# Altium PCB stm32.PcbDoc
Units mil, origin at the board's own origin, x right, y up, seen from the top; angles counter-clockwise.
Board outline 6010.03 x 5085.03 mil, 2 copper layers (Top Layer, Bottom Layer); 115 components, 0 nets, 494 pads, 8 vias.
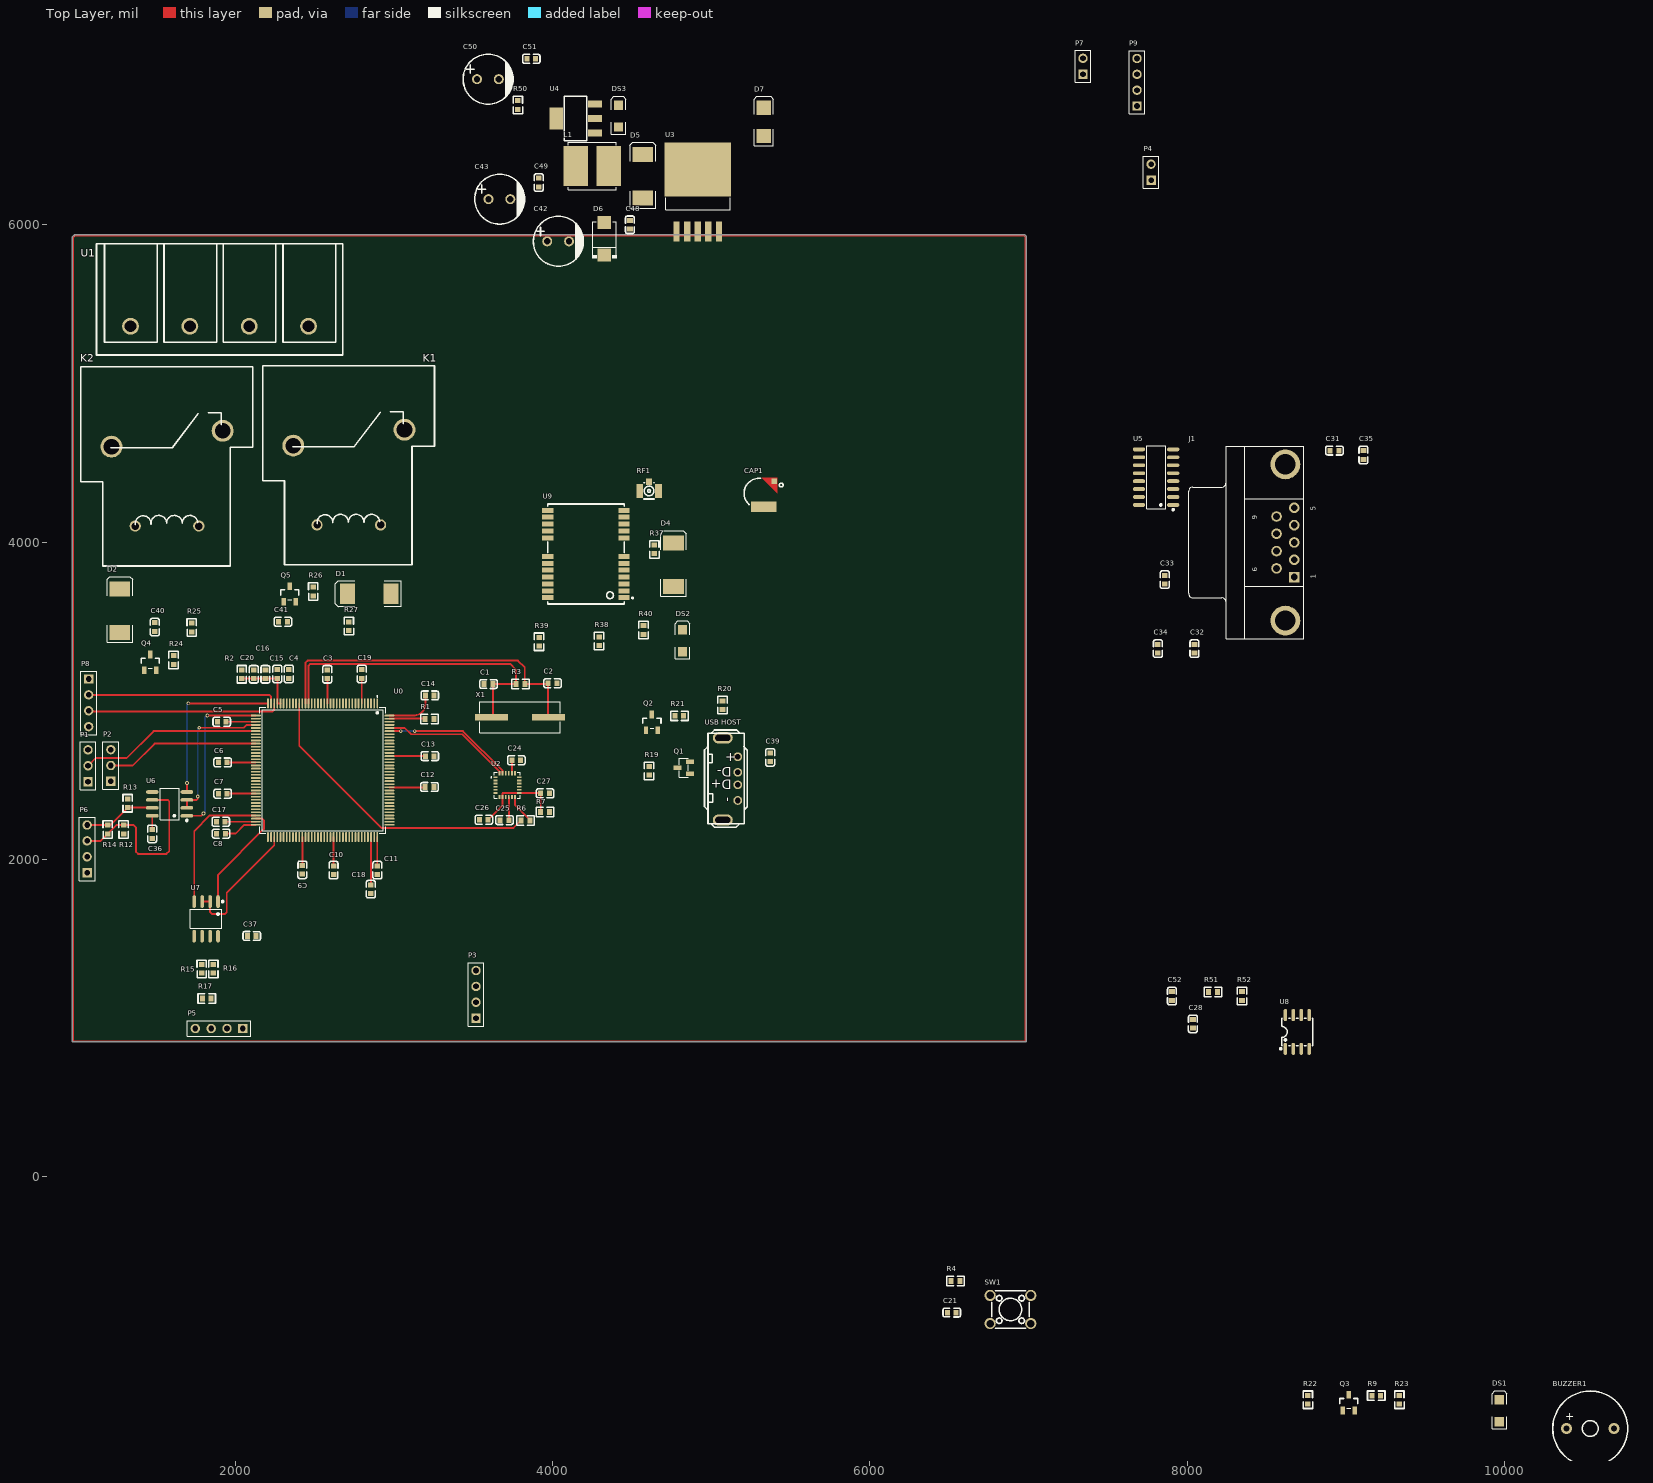
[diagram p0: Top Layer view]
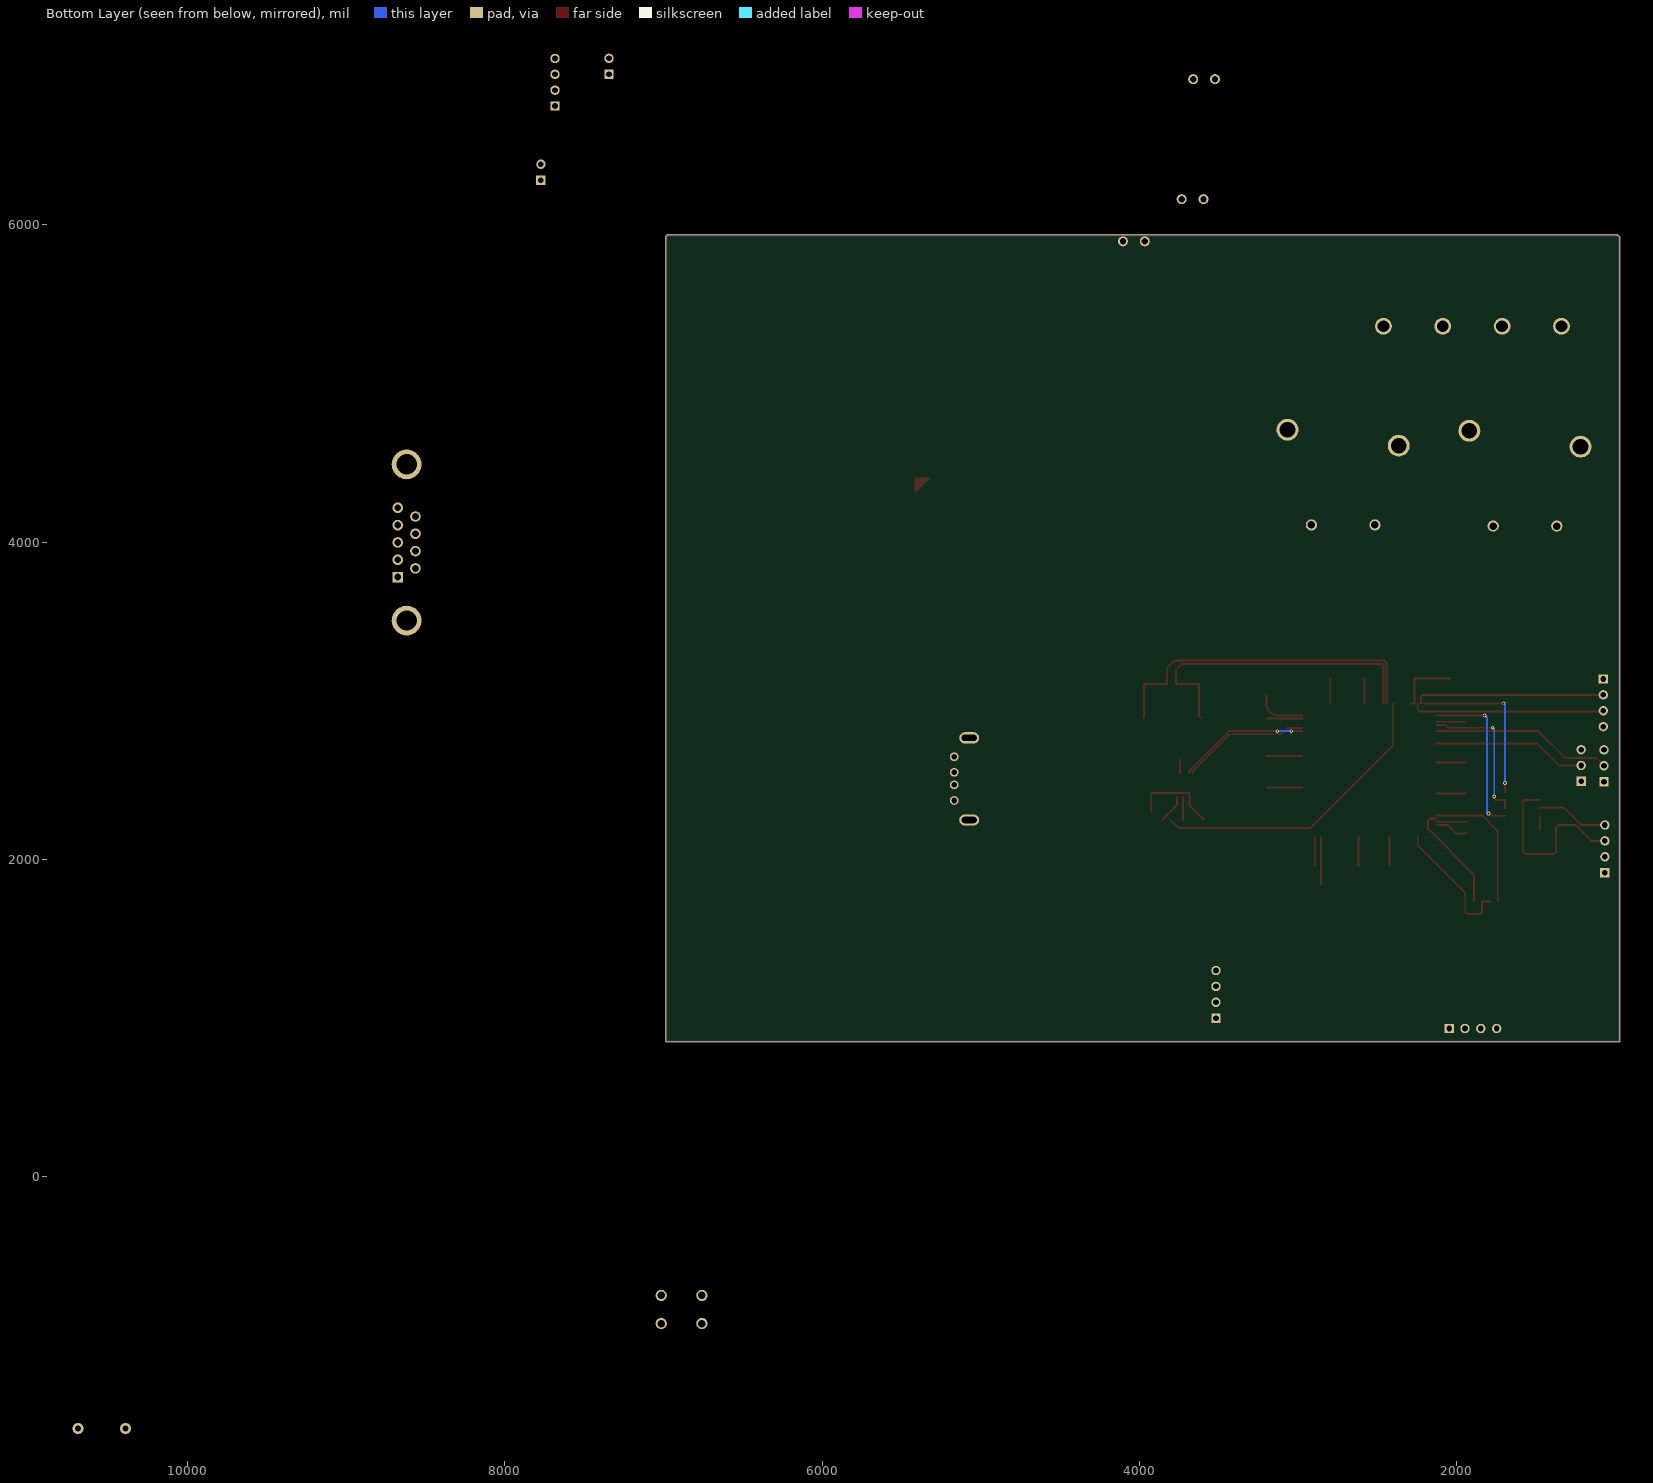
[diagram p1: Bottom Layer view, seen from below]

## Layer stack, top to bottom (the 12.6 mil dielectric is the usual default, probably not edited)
Top Solder: solder mask 0.4, Solder Resist, Dk 3.5
Top Layer: signal copper 1.4
Dielectric 1: dielectric 12.6, FR-4, Dk 4.8
Bottom Layer: signal copper 1.4
Bottom Solder: solder mask 0.4, Solder Resist, Dk 3.5

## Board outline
974.99,855 ccw(c980,855) 980,849.99 6980,849.99 ccw(c6980,855) 6985.02,855 6985.02,5925 ccw(c6980,5925) 6980.02,5930.02 ccw(c6975,5930) 6975,5935.02 990,5935.02 ccw(c990,5930) 986.44,5933.53 986.45,5933.55 976.45,5923.55 976.47,5923.56 ccw(c980,5920) 974.99,5920

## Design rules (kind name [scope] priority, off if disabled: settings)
Clearance [All] p1: gap=10
PolygonConnect [All] p1: connectstyle=Relief reliefconductorwidth=10 reliefentries=4 polygonreliefangle="90 Angle" airgapwidth=10
RoomDefinition STM32F407_V2.0 [InComponentClass('STM32F407_V2.0')] p1: confinementstyle=ConfineIn formatcopy=TRUE lockcomponents=FALSE outline -29946.22,-17788.74 -27946.22,-17788.74 -27946.22,-16788.74 -29946.22,-16788.74
RoutingVias [All] p1: holewidth=28 width=50 viastyle="Through Hole" minholewidth=28 minwidth=50 maxholewidth=28 maxwidth=50
SolderMaskExpansion [All] p1: expansion=4
Width [All] p1: maxlimit=10 minlimit=10 preferedwidth=10
30 further rules are at their usual default settings.

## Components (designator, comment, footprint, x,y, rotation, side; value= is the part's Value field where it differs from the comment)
BUZZER1 "TMB12A03" BUZ-TH_BD12.0-P7.60-D0.6-FD 10539.9,-1586.03 r0 top
C1 "22nF" SMD_CAP_0603 3597.29,3105.71 r180 top
C2 "22nF" SMD_CAP_0603 4000.83,3109.65 r0 top
C3 "100nF" SMD_CAP_0603 2581.54,3166.73 r90 top
C4 "100nF" SMD_CAP_0603 2339.41,3168.7 r90 top
C5 "100nF" SMD_CAP_0603 1916.18,2867.52 r180 top
C6 "100nF" SMD_CAP_0603 1922.08,2611.61 r180 top
C7 "100nF" SMD_CAP_0603 1922.09,2414.76 r180 top
C8 "100nF" SMD_CAP_0603 1912.24,2162.8 r180 top
C9 "100nF" SMD_CAP_0603 2424.06,1934.45 r270 top
C10 "100nF" SMD_CAP_0603 2620.91,1932.48 r90 top
C11 "100nF" SMD_CAP_0603 2896.5,1932.48 r270 top
C12 "100nF" SMD_CAP_0603 3225.24,2456.1 r0 top
C13 "100nF" SMD_CAP_0603 3227.21,2650.98 r0 top
C14 "100nF" SMD_CAP_0603 3227.21,3032.87 r0 top
C15 "10uF" SMD_CAP_0603 2266.57,3168.7 r90 top
C16 "100nF" SMD_CAP_0603 2191.77,3166.73 r90 top
C17 "225nF" SMD_CAP_0603 1910.28,2237.6 r180 top
C18 "225nF" SMD_CAP_0603 2855.16,1812.4 r270 top
C19 "100nF" SMD_CAP_0603 2798.07,3168.7 r270 top
C20 "225nF" SMD_CAP_0603 2118.94,3166.73 r90 top
C21 "100nF" SMD_CAP_0603 6516.38,-855.67 r0 top
C24 "10uF" SMD_CAP_0603 3772.48,2625.39 r180 top
C25 "100nF" SMD_CAP_0603 3697.68,2247.44 r0 top
C26 "10uF" SMD_CAP_0603 3567.76,2249.41 r0 top
C27 "100nF" SMD_CAP_0603 3953.58,2416.73 r180 top
C28 "100nF" SMD_CAP_0603 8036.26,963.98 r90 top
C31 "100nF" SMD_CAP_0603 8927.85,4576.14 r0 top
C32 "100nF" SMD_CAP_0603 8045.97,3328.11 r90 top
C33 "100nF" SMD_CAP_0603 7858.96,3763.15 r90 top
C34 "100nF" SMD_CAP_0603 7815.65,3328.11 r90 top
C35 "100nF" SMD_CAP_0603 9110.92,4548.58 r90 top
C36 "100nF/50V" SMD_CAP_0603 1477.2,2160.83 r270 top
C37 "100nF/50V" SMD_CAP_0603 2105.16,1517.13 r0 top
C39 "100nF" SMD_CAP_0603 5372.73,2643.07 r90 top
C40 "100nF" SMD_CAP_0603 1494.81,3463.93 r90 top
C41 "100nF" SMD_CAP_0603 2301.88,3497.4 r0 top
C42 "680uF" CAP-TH_BD8.0-P3.50-D1.0-FD 4036.15,5895.03 r0 top
C43 "220uF" CAP-TH_BD8.0-P3.50-D1.0-FD 3666.08,6160.78 r0 top
C48 "100nF" SMD_CAP_0603 4488.91,5999.37 r90 top
C49 "100nF" SMD_CAP_0603 3914.11,6265.11 r90 top
C50 "220uF" CAP-TH_BD8.0-P3.50-D1.0-FD 3593.25,6916.68 r0 top
C51 "100nF" SMD_CAP_0603 3866.87,7044.64 r0 top
C52 "10nF/50V/10%" SMD_CAP_0603 7904.27,1139.13 r90 top
CAP1 "70mF" CAP-TH_XH414HG 5392.44,4324.17 r0 top
D1 "Diode" SMC 2846.3,3674.61 r180 top
D2 "Diode" SMC 1274.33,3568.26 r90 top
D4 "Diode" SMC 4762.64,3857.68 r90 top
D5 "Diode" SMC 4569.61,6304.48 r90 top
D6 "SMBJ8.0A" SMB_L4.6-W3.6-LS5.3-RD 4327.49,5910.78 r90 top
D7 "SK54" SMB 5331.43,6647 r90 top
DS1 "LED0" 3.2X1.6X1.1 9967.07,-1473.83 r90 top
DS2 "LED0" 3.2X1.6X1.1 4819.61,3377.32 r90 top
DS3 "LED2" 3.2X1.6X1.1 4416.08,6684.4 r90 top
J1 "D Connector 9" DSUB1.385-2H9 8244.78,3997.4 r90 top
K1 "HF105F-1/012D-1HS" RELAY-TH_HF105F-XXX-1HXXX-XXX 2717.36,4407.68 r0 top
K2 "HF105F-1/012D-1HS" RELAY-TH_HF105F-XXX-1HXXX-XXX 1571.69,4400.98 r0 top
L1 "33uH" IND-SMD_L7.0-W6.8 4250.72,6369.44 r0 top
P1 "Hall1" HDR1X3 1073.66,2490.35 r90 top
P2 "Hall2" HDR1X3 1217.36,2491.93 r90 top
P3 "Header 4" HDR1X4 3518.54,999.8 r90 top
P4 "Header 2" HDR1X2 7772.34,6280.86 r90 top
P5 "Header 4" HDR1X4 2049.65,934.45 r180 top
P6 "Header 4" HDR1X4 1067.76,1916.73 r90 top
P7 "Header 2" HDR1X2 7343.21,6948.18 r90 top
P8 "Header 4" HDR1X4 1077.6,3136.81 r270 top
P9 "Header 4" HDR1X4 7683.77,6747.4 r90 top
Q1 "SI2301" SOT-23-3_L2.9-W1.3-P1.90-LS2.4-BR 4827.46,2578.11 r0 top
Q2 "S8050" NUP2105LT1G 4626.68,2863.54 r0 top
Q3 "S8050" NUP2105LT1G 9018.25,-1422.65 r0 top
Q4 "S8050" NUP2105LT1G 1465.28,3241.49 r0 top
Q5 "S8050" NUP2105LT1G 2345.18,3672.59 r0 top
R1 "0R" SMD_RES_0603 3225.24,2885.24 r180 top
R2 "10R" SMD_RES_0603 2042.17,3166.73 r270 top
R3 "1M" SMD_RES_0603 3798.07,3105.71 r180 top
R4 "10k" SMD_RES_0603 6540,-656.85 r0 top
R6 "1k" SMD_RES_0603 3829.57,2245.47 r180 top
R7 "10R" SMD_RES_0603 3953.58,2298.62 r180 top
R9 "510R" SMD_RES_0603 9191.48,-1379.34 r0 top
R12 "360R" SMD_RES_0603 1298.07,2188.38 r90 top
R13 "360R" SMD_RES_0603 1323.66,2353.74 r90 top
R14 "120R" SMD_RES_0603 1197.68,2188.38 r270 top
R15 "360R" SMD_RES_0603 1790.2,1310.43 r90 top
R16 "360R" SMD_RES_0603 1863.03,1310.43 r270 top
R17 "120R" SMD_RES_0603 1821.69,1123.43 r180 top
R19 "10k" SMD_RES_0603 4609.09,2558.46 r90 top
R20 "100k" SMD_RES_0603 5071.69,2971.85 r90 top
R21 "4.7K" SMD_RES_0603 4799.91,2904.88 r0 top
R22 "10K" SMD_RES_0603 8760.38,-1404.93 r90 top
R23 "1K" SMD_RES_0603 9337.15,-1404.93 r90 top
R24 "4.7K" SMD_RES_0603 1612.91,3257.24 r90 top
R25 "47K" SMD_RES_0603 1727.09,3461.96 r90 top
R26 "4.7K" SMD_RES_0603 2492.82,3688.34 r90 top
R27 "47K" SMD_RES_0603 2717.24,3469.84 r90 top
R37 "120R" SMD_RES_0603 4642.44,3954.09 r90 top
R38 "510R" SMD_RES_0603 4294.13,3375.39 r90 top
R39 "510R" SMD_RES_0603 3916.18,3371.46 r90 top
R40 "510R" SMD_RES_0603 4573.55,3446.22 r90 top
R50 "2K" SMD_RES_0603 3782.22,6753.3 r90 top
R51 "60.4R/5%/1/8W" SMD_RES_0603 8162.14,1164.72 r0 top
R52 "60.4R/5%/1/8W" SMD_RES_0603 8345.21,1139.13 r90 top
RF1 "KH-IPEX-K501-29" ANT-SMD_KH-IPEX-K501-29 4608.98,4351.73 r0 top
SW1 "SW" SW-TH_4P-L6.0-W6.0-P4.50-LS6.5 6886.36,-836.03 r0 top
U0 "STM32F407ZGT6" LQFP-144_L20.0-W20.0-P0.50-LS22.0-BL 2552.01,2562.4 r180 top locked
U1 "DBT50B-9.5-4P" CONN-TH_DBT50B-9.5-4P 1902.4,5359.65 r180 top
U2 "MPU6050" QFN-24_L4.0-W4.0-P0.50-BL-EP2.6 3715.39,2467.91 r270 top
U3 "LM2596R-5.0" TO-263-5_L10.2-W8.6-P1.70-LS14.4-TL 4916.07,6152.91 r90 top
U4 "AMS1117" SOT-223_L6.7-W3.5-P2.30-BR 4146.39,6668.65 r0 top
U5 "MAX3232ID" SOIC-16_L9.9-W3.9-P1.27-LS6.0-BL 7803.84,4408.82 r90 top
U6 "SP3485EEN" SOP-8_L5.0-W4.0-P1.27-LS6.0-BL 1587.44,2349.8 r90 top
U7 "SP3485EEN" SOP-8_L5.0-W4.0-P1.27-LS6.0-BL 1817.76,1625.39 r180 top
U8 "TJA1050T/CM,118" SOIC-8_L5.0-W4.0-P1.27-LS6.0-BL 8693.74,912.8 r0 top
U9 "KH-1612-UB8X" GPSM-SMD_KH-1612-UBXX 4211.46,3924.61 r0 top
"USB HOST" "C16722" USB-A-TH_4P-V-F_13.7MM 5120.77,2507.24 r0 top
X1 "8MHz" HC-49S_L11.4-W4.8 3796.1,2895.08 r180 top

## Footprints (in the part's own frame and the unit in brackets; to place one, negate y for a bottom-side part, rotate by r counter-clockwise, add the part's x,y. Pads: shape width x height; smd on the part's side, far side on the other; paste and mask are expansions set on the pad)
3.2X1.6X1.1 [mm] "SMT LED; 2 Flat Leads"
  rect 1.5x1.5 smd: 1(-1.75,0) 2(1.75,0)
  silkscreen extent -2.9,-1.15 3.2,1.15
ANT-SMD_KH-IPEX-K501-29 [mm]
  rect 1.1x2.2 smd: 1(-1.5,-0.75) 3(1.5,-0.75)
  rect 1x1.05 smd: 2(0,0.75)
  silkscreen extent -0.84,-2.05 0.84,0.55
BUZ-TH_BD12.0-P7.60-D0.6-FD [mm]
  round 1.8 hole 1: 1(-3.8,0) 2(3.8,0)
  silkscreen extent -6,-6 6,6
CAP-TH_BD8.0-P3.50-D1.0-FD [mm]
  round 1.6 hole 1: 1(-1.75,0) 2(1.75,0)
  silkscreen extent -3.96,-4 4.04,4
CAP-TH_XH414HG [mil]
  round 0 smd: 1(-23.48,57.63)
  rect 35x35 smd: 1(5,60)
  rect 161.4x66.93 smd: 2(-60.88,-100.84)
  Top Layer region: -72.69,82.24 25.74,82.24 25.74,-16.19
  silkscreen extent -185,-89 61,77
CONN-TH_DBT50B-9.5-4P [mm]
  round 2.7 hole 1.9: 1(-14.25,0) 2(-4.75,0) 3(4.75,0) 4(14.25,0)
  silkscreen extent -19.7,-13.21 19.7,4.6
DSUB1.385-2H9 [mm] "Connector; D Subminiature; 9 Position; Right Angle; Pitch 1.385 mm"
  rect 1.69x1.69 hole 1.09: 1(-5.54,-10.92)
  round 1.69 hole 1.09: 2(-2.77,-10.92) 3(0,-10.92) 4(2.77,-10.92) 5(5.54,-10.92) 6(-4.155,-8.08) 7(-1.385,-8.08) 8(1.385,-8.08) 9(4.155,-8.08)
  round 4.76 hole 3.26: 10(-12.495,-9.5) 11(12.495,-9.5)
  silkscreen extent -15.4,-12.4 15.4,6
GPSM-SMD_KH-1612-UBXX [mm]
  rect 1.8x0.8 smd: 1(6.1,-7) 2(6.1,-5.9) 3(6.1,-4.8) 4(6.1,-3.7) 5(6.1,-2.6) 6(6.1,-1.5) 7(6.1,-0.4) 8(6.1,2.6) 9(6.1,3.7) 10(6.1,4.8) 11(6.1,5.9) 12(6.1,7) 13(-6.1,7) 14(-6.1,5.9) 15(-6.1,4.8) 16(-6.1,3.7) 17(-6.1,2.6) 18(-6.1,-0.4) 19(-6.1,-1.5) 20(-6.1,-2.6) 21(-6.1,-3.7) 22(-6.1,-4.8) 23(-6.1,-5.9) 24(-6.1,-7)
  silkscreen extent -6.1,-8 7.58,8
HC-49S_L11.4-W4.8 [mm] "晶振8M"
  rect 5.274x1.02 smd: 1(4.553,0) 2(-4.553,0)
  silkscreen extent -6.43,-2.48 6.43,2.48
HDR1X2 [mm] "Connector; Header; 2 Position"
  rect 1.5x1.5 hole 0.9: 1(0,0)
  round 1.5 hole 0.9: 2(2.54,0)
  silkscreen extent -1.27,-1.27 3.81,1.27
HDR1X3 [mm] "Connector; Header; 3 Position"
  rect 1.5x1.5 hole 0.9: 1(0,0)
  round 1.5 hole 0.9: 2(2.54,0) 3(5.08,0)
  silkscreen extent -1.27,-1.27 6.35,1.27
HDR1X4 [mm] "Connector; Header; 4 Position"
  rect 1.5x1.5 hole 0.9: 1(0,0)
  round 1.5 hole 0.9: 2(2.54,0) 3(5.08,0) 4(7.62,0)
  silkscreen extent -1.27,-1.27 8.89,1.27
IND-SMD_L7.0-W6.8 [mm]
  rect 3.924x6.42 smd: 1(2.628,0) 2(-2.628,0)
  silkscreen extent -3.83,-3.83 3.83,3.83
LQFP-144_L20.0-W20.0-P0.50-LS22.0-BL [mm] "MCU"
  oval 0.28x1.6 smd: 1(-8.75,-10.7) 2(-8.25,-10.7) 3(-7.75,-10.7) 4(-7.25,-10.7) 5(-6.75,-10.7) 6(-6.25,-10.7) 7(-5.75,-10.7) 8(-5.25,-10.7) 9(-4.75,-10.7) 10(-4.25,-10.7) 11(-3.75,-10.7) 12(-3.25,-10.7) 13(-2.75,-10.7) 14(-2.25,-10.7) 15(-1.75,-10.7) 16(-1.25,-10.7) 17(-0.75,-10.7) 18(-0.25,-10.7) 19(0.25,-10.7) 20(0.75,-10.7) 21(1.25,-10.7) 22(1.75,-10.7) 23(2.25,-10.7) 24(2.75,-10.7) 25(3.25,-10.7) 26(3.75,-10.7) 27(4.25,-10.7) 28(4.75,-10.7) 29(5.25,-10.7) 30(5.75,-10.7) 31(6.25,-10.7) 32(6.75,-10.7) 33(7.25,-10.7) 34(7.75,-10.7) 35(8.25,-10.7) 36(8.75,-10.7) 73(8.75,10.7) 74(8.25,10.7) 75(7.75,10.7) 76(7.25,10.7) 77(6.75,10.7) 78(6.25,10.7) 79(5.75,10.7) 80(5.25,10.7) 81(4.75,10.7) 82(4.25,10.7) 83(3.75,10.7) 84(3.25,10.7) 85(2.75,10.7) 86(2.25,10.7) 87(1.75,10.7) 88(1.25,10.7) 89(0.75,10.7) 90(0.25,10.7) 91(-0.25,10.7) 92(-0.75,10.7) 93(-1.25,10.7) 94(-1.75,10.7) 95(-2.25,10.7) 96(-2.75,10.7) 97(-3.25,10.7) 98(-3.75,10.7) 99(-4.25,10.7) 100(-4.75,10.7) 101(-5.25,10.7) 102(-5.75,10.7) 103(-6.25,10.7) 104(-6.75,10.7) 105(-7.25,10.7) 106(-7.75,10.7) 107(-8.25,10.7) 108(-8.75,10.7)
  oval 1.6x0.28 smd: 37(10.7,-8.75) 38(10.7,-8.25) 39(10.7,-7.75) 40(10.7,-7.25) 41(10.7,-6.75) 42(10.7,-6.25) 43(10.7,-5.75) 44(10.7,-5.25) 45(10.7,-4.75) 46(10.7,-4.25) 47(10.7,-3.75) 48(10.7,-3.25) 49(10.7,-2.75) 50(10.7,-2.25) 51(10.7,-1.75) 52(10.7,-1.25) 53(10.7,-0.75) 54(10.7,-0.25) 55(10.7,0.25) 56(10.7,0.75) 57(10.7,1.25) 58(10.7,1.75) 59(10.7,2.25) 60(10.7,2.75) 61(10.7,3.25) 62(10.7,3.75) 63(10.7,4.25) 64(10.7,4.75) 65(10.7,5.25) 66(10.7,5.75) 67(10.7,6.25) 68(10.7,6.75) 69(10.7,7.25) 70(10.7,7.75) 71(10.7,8.25) 72(10.7,8.75) 109(-10.7,8.75) 110(-10.7,8.25) 111(-10.7,7.75) 112(-10.7,7.25) 113(-10.7,6.75) 114(-10.7,6.25) 115(-10.7,5.75) 116(-10.7,5.25) 117(-10.7,4.75) 118(-10.7,4.25) 119(-10.7,3.75) 120(-10.7,3.25) 121(-10.7,2.75) 122(-10.7,2.25) 123(-10.7,1.75) 124(-10.7,1.25) 125(-10.7,0.75) 126(-10.7,0.25) 127(-10.7,-0.25) 128(-10.7,-0.75) 129(-10.7,-1.25) 130(-10.7,-1.75) 131(-10.7,-2.25) 132(-10.7,-2.75) 133(-10.7,-3.25) 134(-10.7,-3.75) 135(-10.7,-4.25) 136(-10.7,-4.75) 137(-10.7,-5.25) 138(-10.7,-5.75) 139(-10.7,-6.25) 140(-10.7,-6.75) 141(-10.7,-7.25) 142(-10.7,-7.75) 143(-10.7,-8.25) 144(-10.7,-8.75)
  silkscreen extent -10.08,-11.9 10.08,10.08
NUP2105LT1G [mm]
  rect 0.7x1.25 smd: 1(-0.95,-1.25) 2(0.95,-1.25) 3(0,1.25)
  silkscreen extent -1.46,-0.9 1.46,0.65
QFN-24_L4.0-W4.0-P0.50-BL-EP2.6 [mm]
  rect 0.28x0.665 smd: 1(-1.25,-1.907) 2(-0.75,-1.907) 3(-0.25,-1.907) 4(0.25,-1.907) 5(0.75,-1.907) 6(1.25,-1.907) 13(1.25,1.907) 14(0.75,1.907) 15(0.25,1.907) 16(-0.25,1.907) 17(-0.75,1.907) 18(-1.25,1.907)
  rect 0.665x0.28 smd: 7(1.907,-1.25) 8(1.907,-0.75) 9(1.907,-0.25) 10(1.907,0.25) 11(1.907,0.75) 12(1.907,1.25) 19(-1.907,1.25) 20(-1.907,0.75) 21(-1.907,0.25) 22(-1.907,-0.25) 23(-1.907,-0.75) 24(-1.907,-1.25)
  silkscreen extent -2.08,-2.61 2.08,2.08
RELAY-TH_HF105F-XXX-1HXXX-XXX [mm]
  round 3.5 hole 2.5: 2(8.9,7.62) 5(-8.9,5.08)
  round 1.8 hole 1.2: 3(5.08,-7.62) 4(-5.1,-7.62)
  silkscreen extent -13.8,-14.02 13.7,17.88
SMB [mm] "DO-214-AA/SMB; 2 C-Bend Leads; Body 5.3 x 3.6 mm, inc. leads (LxW)"
  rect 2.3x2.3 smd: 1(-2.25,0) 2(2.25,0)
  silkscreen extent -3.8,-1.55 4.1,1.55
SMB_L4.6-W3.6-LS5.3-RD [mil]
  rect 80.61x86.31 smd: 1(-102.71,0) 2(102.71,0)
  silkscreen extent -123,-77 108,77
SMC [mm] "DO-214-AB/SMC; 2 C-Bend Leads; Body 7.9 x 5.9 mm, inc. leads (LxW)"
  rect 2.4x3.3 smd: 1(-3.475,0) 2(3.475,0)
  silkscreen extent -5.07,-2.05 5.43,2.05
SMD_CAP_0603 [mm]
  rect 0.8x0.9 smd: 1(-0.7,0) 2(0.7,0)
  silkscreen extent -1.4,-0.7 1.4,0.72
SMD_RES_0603 [mm]
  rect 0.8x0.9 smd: 1(-0.7,0) 2(0.7,0)
  silkscreen extent -1.4,-0.75 1.4,0.76
SOIC-8_L5.0-W4.0-P1.27-LS6.0-BL [mil]
  oval 22.38x76.78 smd: 1(-75,-106.5) 2(-25,-106.5) 3(25,-106.5) 4(75,-106.5) 5(75,106.5) 6(25,106.5) 7(-25,106.5) 8(-75,106.5)
  silkscreen extent -110,-112 98,87
SOIC-16_L9.9-W3.9-P1.27-LS6.0-BL [mil]
  oval 23.7x77.6 smd: 1(-175,-107.7) 2(-125,-107.7) 3(-75,-107.7) 4(-25,-107.7) 5(25,-107.7) 6(75,-107.7) 7(125,-107.7) 8(175,-107.7) 9(175,107.7) 10(125,107.7) 11(75,107.7) 12(25,107.7) 13(-25,107.7) 14(-75,107.7) 15(-125,107.7) 16(-175,107.7)
  silkscreen extent -211,-114 198,60
SOP-8_L5.0-W4.0-P1.27-LS6.0-BL [mil]
  oval 22.6x80.14 smd: 1(-75,-108.97) 2(-25,-108.97) 3(25,-108.97) 4(75,-108.97) 5(75,108.97) 6(25,108.97) 7(-25,108.97) 8(-75,108.97)
  silkscreen extent -110,-115 99,60
SOT-23-3_L2.9-W1.3-P1.90-LS2.4-BR [mm]
  rect 1.25x0.7 smd: 1(1,-0.95) 2(1,0.95) 3(-1,0)
  silkscreen extent -0.73,-1.53 0.73,1.53
SOT-223_L6.7-W3.5-P2.30-BR [mm]
  rect 2.2x1.1 smd: 1(3.099,-2.3) 2(3.099,0) 3(3.099,2.3)
  rect 2.2x3.5 smd: 4(-3.099,0)
  silkscreen extent -1.8,-3.55 1.8,3.55
SW-TH_4P-L6.0-W6.0-P4.50-LS6.5 [mm]
  round 1.8 hole 1.2: 1(-3.25,2.25) 2(3.25,2.25) 3(-3.25,-2.25) 4(3.25,-2.25)
  silkscreen extent -3,-3 3,3
TO-263-5_L10.2-W8.6-P1.70-LS14.4-TL [mm]
  rect 3.183x1.02 smd: 1(-4.953,3.4) 2(-4.953,1.7) 3(-4.953,0) 4(-4.953,-1.7) 5(-4.953,-3.4)
  rect 8.705x10.587 smd: 6(4.953,0)
  silkscreen extent -1.52,-5.17 0.45,5.17
USB-A-TH_4P-V-F_13.7MM [mm]
  round 1.4 hole 0.92: 1(1.2,3.551) 2(1.2,1.052) 3(1.2,-0.947) 4(1.2,-3.447)
  oval 3.2x1.8 hole 1 slot 2.4 at 0 deg: 5(-1.2,-6.571) 6(-1.2,6.571)
  silkscreen extent -4.12,-7.74 2.74,7.83

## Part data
BUZZER1: "蜂鸣器"
C1 C2 C3 C4 C5 C6 C7 C8 C9 C10 C11 C12 C13 C14 C15 C16 C17 C18 C21 C24 C25 C26 C27 C28 C31 C32 C33 C34 C35 C36 C37 C39 C40 C41 C52: library part Cap, "Capacitor"
C19 C20: library part Cap, "陶瓷电容"
CAP1: library part "Super Cap"
D1 D2 D4 D5: "Default Diode"
D6: library part SMBJ8.0A_C726816
D7: library part "D Schottky", "Schottky Diode"
DS1 DS2: library part LED2, "Typical RED, GREEN, YELLOW, AMBER GaAs LED"
DS3: "Typical RED, GREEN, YELLOW, AMBER GaAs LED"
J1: "Receptacle Assembly, 9 Position, Right Angle"
K1 K2: "继电器"
P1 P2: library part "Header 3", "Header, 3-Pin"
P3 P5 P6 P8 P9: "Header, 4-Pin"
P4 P7: "Header, 2-Pin"
Q1: library part SI2301_C427391
Q2 Q3 Q4 Q5: library part NPN, "NPN Bipolar Transistor"
R1 R2 R3 R4 R6 R7: library part Res1, "Resistor"
R9 R40 R50: library part Res1, "水泥电阻"
R12 R13 R14 R15 R16 R17 R19 R20 R21 R22 R23 R24 R25 R26 R27 R37 R38 R39 R51 R52: library part "Res Semi", "Semiconductor Resistor"
RF1: "天线插座"
U0: "MCU"
U1: "接线端子"
U2: library part MPU-6050_C24112, "陀螺仪"
U4: library part ASM1117
U9: "GPS"
"USB HOST": "USB_HOST"
X1: "贴片晶振"

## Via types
v1: diameter 23.62, hole 11.81, Top Layer to Bottom Layer, tented both sides, 8 vias

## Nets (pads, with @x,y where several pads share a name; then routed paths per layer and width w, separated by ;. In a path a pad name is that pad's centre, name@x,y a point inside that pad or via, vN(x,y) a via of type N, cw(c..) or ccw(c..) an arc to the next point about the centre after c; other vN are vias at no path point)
pads on no net: "USB HOST.1" "USB HOST.2" "USB HOST.3" "USB HOST.4" "USB HOST.5" "USB HOST.6" BUZZER1.1 BUZZER1.2 C1.1 C1.2 C2.1 C2.2 C3.1 C3.2 C4.1 C4.2 C5.1 C5.2 C6.1 C6.2 C7.1 C7.2 C8.1 C8.2 C9.1 C9.2 C10.1 C10.2 C11.1 C11.2 C12.1 C12.2 C13.1 C13.2 C14.1 C14.2 C15.1 C15.2 C16.1 C16.2 C17.1 C17.2 C18.1 C18.2 C19.1 C19.2 C20.1 C20.2 C21.1 C21.2 C24.1 C24.2 C25.1 C25.2 C26.1 C26.2 C27.1 C27.2 C28.1 C28.2 C31.1 C31.2 C32.1 C32.2 C33.1 C33.2 C34.1 C34.2 C35.1 C35.2 C36.1 C36.2 C37.1 C37.2 C39.1 C39.2 C40.1 C40.2 C41.1 C41.2 C42.1 C42.2 C43.1 C43.2 C48.1 C48.2 C49.1 C49.2 C50.1 C50.2 C51.1 C51.2 C52.1 C52.2 CAP1.1 CAP1.2 D1.1 D1.2 D2.1 D2.2 D4.1 D4.2 D5.1 D5.2 D6.1 D6.2 D7.1 D7.2 DS1.1 DS1.2 DS2.1 DS2.2 DS3.1 DS3.2 J1.1 J1.2 J1.3 J1.4 J1.5 J1.6 J1.7 J1.8 J1.9 J1.10 J1.11 K1.2 K1.3 K1.4 K1.5 K2.2 K2.3 K2.4 K2.5 L1.1 L1.2 P1.1 P1.2 P1.3 P2.1 P2.2 P2.3 P3.1 P3.2 P3.3 P3.4 P4.1 P4.2 P5.1 P5.2 P5.3 P5.4 P6.1 P6.2 P6.3 P6.4 P7.1 P7.2 P8.1 P8.2 P8.3 P8.4 P9.1 P9.2 P9.3 P9.4 Q1.1 Q1.2 Q1.3 Q2.1 Q2.2 Q2.3 Q3.1 Q3.2 Q3.3 Q4.1 Q4.2 Q4.3 Q5.1 Q5.2 Q5.3 R1.1 R1.2 R2.1 R2.2 R3.1 R3.2 R4.1 R4.2 R6.1 R6.2 R7.1 R7.2 R9.1 R9.2 R12.1 R12.2 R13.1 R13.2 R14.1 R14.2 R15.1 R15.2 R16.1 R16.2 R17.1 R17.2 R19.1 R19.2 R20.1 R20.2 R21.1 R21.2 R22.1 R22.2 R23.1 R23.2 R24.1 R24.2 R25.1 R25.2 R26.1 R26.2 R27.1 R27.2 R37.1 R37.2 R38.1 R38.2 R39.1 R39.2 R40.1 R40.2 R50.1 R50.2 R51.1 R51.2 R52.1 R52.2 RF1.1 RF1.2 RF1.3 SW1.1 SW1.2 SW1.3 SW1.4 U0.1 U0.2 U0.3 U0.4 U0.5 U0.6 U0.7 U0.8 U0.9 U0.10 U0.11 U0.12 U0.13 U0.14 U0.15 U0.16 U0.17 U0.18 U0.19 U0.20 U0.21 U0.22 U0.23 U0.24 U0.25 U0.26 U0.27 U0.28 U0.29 U0.30 U0.31 U0.32 U0.33 U0.34 U0.35 U0.36 U0.37 U0.38 U0.39 U0.40 U0.41 U0.42 U0.43 U0.44 U0.45 U0.46 U0.47 U0.48 U0.49 U0.50 U0.51 U0.52 U0.53 U0.54 U0.55 U0.56 U0.57 U0.58 U0.59 U0.60 U0.61 U0.62 U0.63 U0.64 U0.65 U0.66 U0.67 U0.68 U0.69 U0.70 U0.71 U0.72 U0.73 U0.74 U0.75 U0.76 U0.77 U0.78 U0.79 U0.80 U0.81 U0.82 U0.83 U0.84 U0.85 U0.86 U0.87 U0.88 U0.89 U0.90 U0.91 U0.92 U0.93 U0.94 U0.95 U0.96 U0.97 U0.98 U0.99 U0.100 U0.101 U0.102 U0.103 U0.104 U0.105 U0.106 U0.107 U0.108 U0.109 U0.110 U0.111 U0.112 U0.113 U0.114 U0.115 U0.116 U0.117 U0.118 U0.119 U0.120 U0.121 U0.122 U0.123 U0.124 U0.125 U0.126 U0.127 U0.128 U0.129 U0.130 U0.131 U0.132 U0.133 U0.134 U0.135 U0.136 U0.137 U0.138 U0.139 U0.140 U0.141 U0.142 U0.143 U0.144 U1.1 U1.2 U1.3 U1.4 U2.1 U2.2 U2.3 U2.4 U2.5 U2.6 U2.7 U2.8 U2.9 U2.10 U2.11 U2.12 U2.13 U2.14 U2.15 U2.16 U2.17 U2.18 U2.19 U2.20 U2.21 U2.22 U2.23 U2.24 U3.1 U3.2 U3.3 U3.4 U3.5 U3.6 U4.1 U4.2 U4.3 U4.4 U5.1 U5.2 U5.3 U5.4 U5.5 U5.6 U5.7 U5.8 U5.9 U5.10 U5.11 U5.12 U5.13 U5.14 U5.15 U5.16 U6.1 U6.2 U6.3 U6.4 U6.5 U6.6 U6.7 U6.8 U7.1 U7.2 U7.3 U7.4 U7.5 U7.6 U7.7 U7.8 U8.1 U8.2 U8.3 U8.4 U8.5 U8.6 U8.7 U8.8 U9.1 U9.2 U9.3 U9.4 U9.5 U9.6 U9.7 U9.8 U9.9 U9.10 U9.11 U9.12 U9.13 U9.14 U9.15 U9.16 U9.17 U9.18 U9.19 U9.20 U9.21 U9.22 U9.23 U9.24 X1.1 X1.2
copper on no net: | length 46007.7
  Top Layer w10: 6925,5930 6975,5930 6980,5925 6980,4735 6980,855 980,855 980,5920 990,5930 6935,5930
  Top Layer w11.81: 1067.76,2116.73 1153.58,2116.73 1197.68,2160.83 1252.79,2215.94 1298.07,2215.94 1361.07,2215.94 1374.84,2202.17 1374.84,2048.62 1388.62,2034.84 1567.76,2034.84 1585.47,2052.56 1585.47,2365.55 1577.01,2374.02 1577.01,2374.8 1478.47,2374.8 ; 1067.76,2216.73 1196.89,2216.73 1197.68,2215.94 1213.42,2215.94 1323.66,2326.18 1477.1,2326.18 1478.47,2324.8 ; 1073.66,2590.35 1122.48,2639.17 1317.76,2639.17 1487.05,2808.46 2130.75,2808.46 ; 1077.6,2936.81 1081.93,2932.48 2237.05,2932.48 2246.89,2942.32 2246.89,2983.66 ; 1077.6,3036.81 2215.39,3036.81 2227.2,3025 2227.2,2983.66 ; 1217.36,2591.93 1355.16,2591.93 1492.95,2729.72 2130.75,2729.72 ; 1477.2,2188.39 1478.47,2189.66 1478.47,2274.8 ; 1696.41,2274.8 1788.03,2274.8 v1(1802.01,2288.78) ; 1696.41,2324.8 1696.41,2374.8 1697.79,2373.43 1756.73,2373.43 1764.61,2381.3 v1(1764.61,2397.05) ; 1696.41,2424.8 1697.68,2426.07 v1(1697.68,2481.69) ; v1(1705.55,2983.66) 2207.52,2983.66 ; 1742.76,1734.36 1742.76,2178.35 1841.38,2276.97 2130.75,2276.97 ; v1(1774.45,2830.12) 2055.94,2830.12 2073.66,2847.83 2130.75,2847.83 ; 1792.76,1734.36 1842.76,1734.36 1842.76,1667.32 1855.16,1654.92 1935.87,1654.92 1947.68,1666.73 1947.68,1788.78 2246.89,2087.99 2246.89,2141.14 ; v1(1825.63,2906.89) 2130.75,2906.89 ; 1892.76,1734.36 1892.76,1903.15 2181.93,2192.32 2181.93,2245.47 2170.12,2257.28 2130.75,2257.28 ; 1937.83,2237.6 2130.75,2237.6 ; 1939.8,2162.8 2002.8,2162.8 2057.91,2217.91 2130.75,2217.91 ; 1943.74,2867.52 2130.75,2867.52 ; 1949.65,2414.76 2130.75,2414.76 ; 1949.64,2611.61 2130.75,2611.61 ; 2042.17,3139.18 2118.93,3139.18 ; 2118.94,3139.17 2191.77,3139.17 ; 2191.77,3139.18 2264.61,3139.18 2266.57,3141.14 2266.57,2983.66 2286.26,2983.66 ; 2404.37,2983.66 2404.37,2715.95 2922.09,2198.23 3754.77,2198.23 3802.01,2245.47 ; 2424.05,1962.01 2424.05,2141.14 ; 2443.74,2983.66 2443.74,3239.85 2457.24,3253.35 3782.32,3253.35 3825.63,3210.04 3825.63,3105.71 3969.33,3105.71 3973.27,3109.65 3973.27,2897.16 3975.35,2895.08 ; 2463.42,2983.66 2463.42,3221.85 2473.27,3231.69 3733.11,3231.69 3770.51,3194.29 3770.51,3105.71 3624.84,3105.71 3624.84,2903.07 3616.85,2895.08 ; 2581.54,2983.66 2581.54,3139.17 ; 2620.91,1960.04 2620.91,2141.14 ; 2798.07,2983.66 2798.07,3141.14 ; 2855.16,1839.96 2857.13,1841.93 2857.13,2141.14 ; 2896.5,1960.04 2896.5,2141.14 ; 2973.27,2454.13 3195.71,2454.13 3197.68,2456.1 ; 2973.27,2650.98 3199.65,2650.98 ; 2973.27,2808.46 v1(3044.13,2808.46) ; 2973.27,2828.15 3069.72,2828.15 3109.09,2788.78 3431.93,2788.78 3666.18,2554.53 3666.18,2543.01 ; 2973.27,2887.2 3195.71,2887.2 3197.68,2885.24 ; 2973.27,2906.89 3126.87,2906.89 ccw(c3126.87,2979.67) 3199.65,2979.67 3199.65,3032.87 ; v1(3132.72,2808.46) 3435.87,2808.46 3685.87,2558.46 3685.87,2543.01 ; 3595.31,2249.41 3685.87,2339.96 3685.87,2392.82 3685.87,2416.73 3687.83,2418.7 3790.49,2418.7 3924.06,2418.7 3926.03,2416.73 3926.03,2298.62 ; 3725.24,2247.44 3725.24,2392.81 ; 3744.92,2543.01 3744.92,2625.39 ; 3764.61,2392.82 3764.61,2341.93 3857.13,2249.41 3857.13,2245.47
  Bottom Layer w11.81: v1(1697.68,2481.69) 1697.68,2975.79 v1(1705.55,2983.66) ; v1(1764.61,2397.05) 1764.61,2822.24 1772.48,2830.12 v1(1774.45,2830.12) ; v1(1802.01,2288.78) 1811.85,2298.62 1811.85,2897.05 1817.76,2902.95 1825.63,2902.95 v1(1825.63,2906.89) ; v1(3044.13,2808.46) v1(3132.72,2808.46)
